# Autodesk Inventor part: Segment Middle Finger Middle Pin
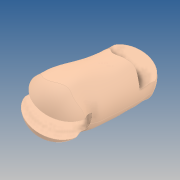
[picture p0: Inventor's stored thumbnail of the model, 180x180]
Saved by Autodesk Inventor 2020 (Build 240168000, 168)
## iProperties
Created: 2019-10
Part Number: Segment Middle Finger Middle Pin
Material: GFRP
Document SubType Name: Modeling
Designer: yello
Density: 1.75 g/cm^3
Appearance: Default
Author: yello
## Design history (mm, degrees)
feature "Paliczek SR"
body "Solid1"
